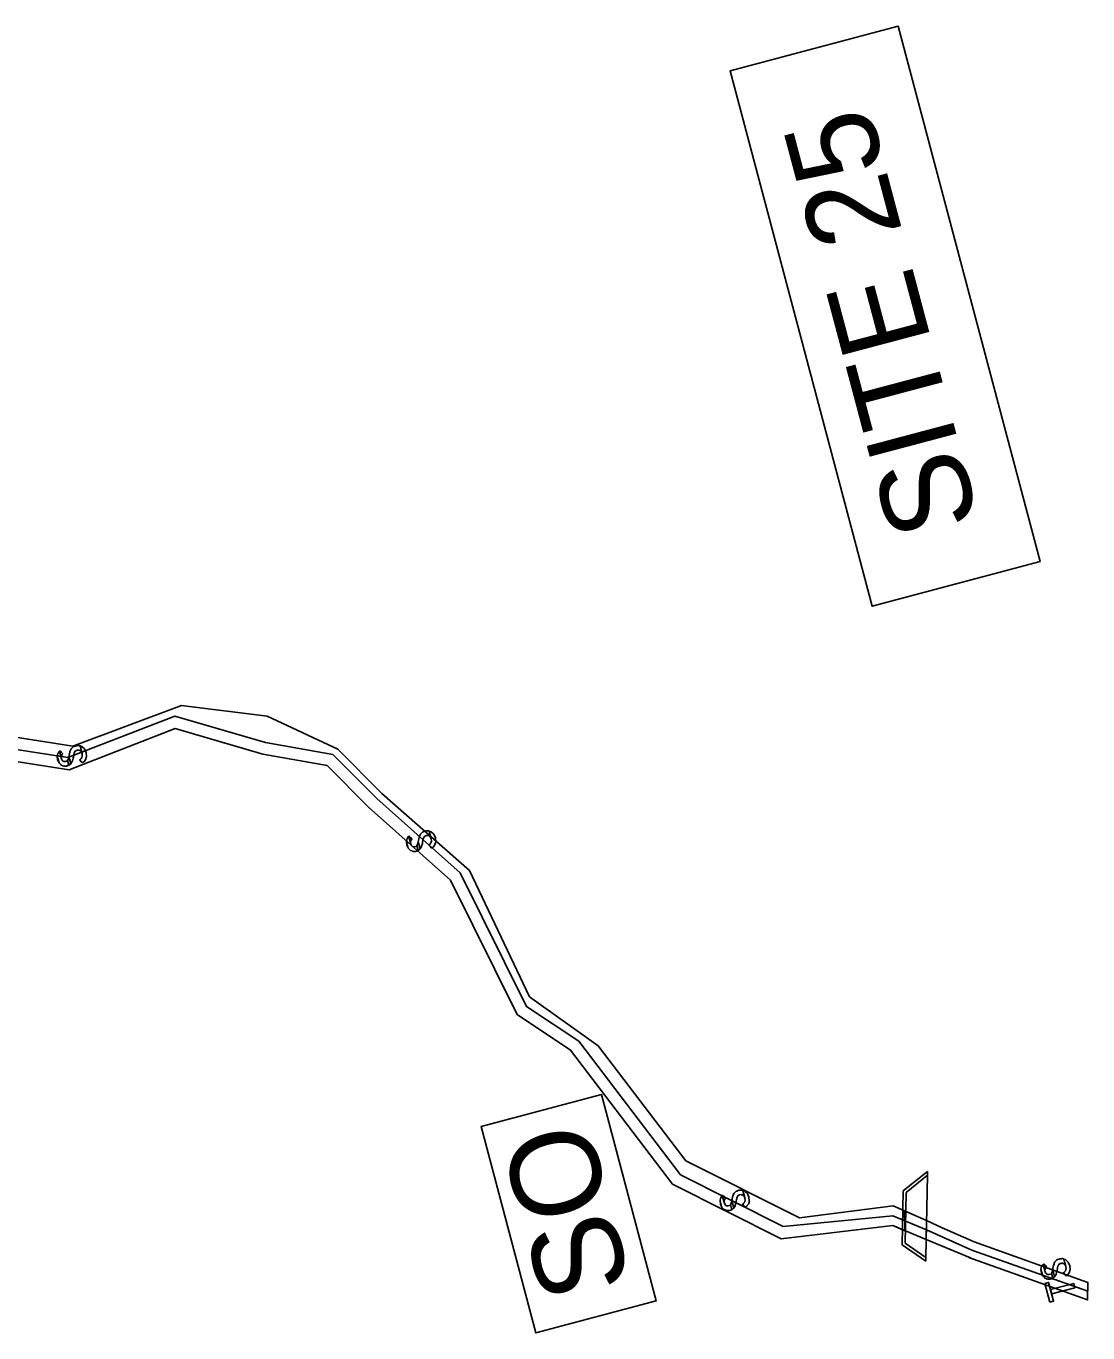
# Model space of a CAD drawing. Extents: x 474218 to 481634, y 484357 to 504997.
# Drawn here: x 474683.1 to 474860.7, y 503504.1 to 503722.6 of the extents above; entities that cross this region are included whole.
import ezdxf

# ---------------------------------------------------------------- set-up
doc = ezdxf.new("R2010")
doc.units = 0
for name, color, linetype in [('Exist Hydro Jurisdictional Stream or Body of Water', 7, 'Continuous'), ('Old_Level_29', 7, 'Continuous'), ('Prop Earthen Structure Impacts In Surface Waters Hatching CELL', 7, 'Continuous'), ('Prop Grid Mask', 7, 'Continuous'), ('Scratch_Level_4', 7, 'Continuous'), ('Temp Earthen Structure Impacts In Surface Waters Hatching CELL', 7, 'Continuous')]:
    doc.layers.add(name, color=color, linetype=linetype)

msp = doc.modelspace()

# ---------------------------------------------------------------- linework, layer by layer
at = {"layer": 'Exist Hydro Jurisdictional Stream or Body of Water'}
msp.add_lwpolyline([(474768.41, 503504.07), (474759.25, 503538.58), (474779.37, 503543.93), (474788.54, 503509.41)], close=True, dxfattribs=at)
at = {"layer": 'Old_Level_29'}
msp.add_lwpolyline([(474824.67, 503625.6), (474800.88, 503715.15), (474828.99, 503722.62), (474852.78, 503633.07)], close=True, dxfattribs=at)
at = {"layer": 'Prop Earthen Structure Impacts In Surface Waters Hatching CELL'}
msp.add_line((474833.71, 503519.66), (474833.77, 503522.84), dxfattribs=at)
for points in [[(474833.77, 503522.84), (474828.15, 503525.32), (474812.53, 503523.33), (474793.51, 503532.82), (474778.81, 503552.07), (474767.33, 503560.28), (474757.3, 503581.41), (474742.63, 503594.3), (474735.29, 503601.71), (474723.46, 503607.23), (474709.13, 503608.98), (474690.95, 503602.21), (474676.66, 503604.42)], [(474676.08, 503600.47), (474690.35, 503598.26), (474708.09, 503605.12), (474722.74, 503600.88), (474733.47, 503598.97), (474740.42, 503591.99), (474754.12, 503579.78), (474765.26, 503557.3), (474774.22, 503551.36), (474791.27, 503528.92), (474809.41, 503519.82), (474828.1, 503522), (474833.71, 503519.66)]]:
    msp.add_lwpolyline(points, dxfattribs=at)
for points in [[(474690.14, 503598.94), (474690.3, 503598.99), (474690.07, 503599.85), (474689.93, 503599.71), (474689.68, 503599.62), (474689.67, 503599.62), (474689.6, 503599.62), (474689.42, 503599.64), (474689.35, 503599.7), (474689.25, 503599.76), (474689.2, 503599.8), (474689.18, 503599.83), (474689.12, 503599.93), (474689.05, 503600.07), (474688.71, 503601.33), (474688.65, 503601.27), (474688.47, 503601.01), (474688.43, 503600.95), (474688.34, 503600.51), (474688.64, 503599.38), (474688.92, 503599.1), (474689, 503599.03), (474689.27, 503598.92), (474689.36, 503598.88), (474689.41, 503598.86), (474689.44, 503598.85), (474689.45, 503598.85), (474689.49, 503598.85), (474689.57, 503598.85), (474689.63, 503598.85), (474689.81, 503598.85), (474689.87, 503598.85), (474689.89, 503598.85)], [(474689.13, 503600.74), (474689.26, 503600.92), (474689.01, 503601.19), (474688.93, 503601.28), (474688.81, 503601.41), (474688.78, 503601.38), (474688.77, 503601.38), (474688.75, 503601.36), (474688.71, 503601.33), (474689.05, 503600.07), (474689, 503600.4), (474689.02, 503600.45), (474689.02, 503600.47), (474689.04, 503600.54), (474689.09, 503600.68)], [(474692.36, 503601.23), (474692.49, 503600.96), (474692.15, 503602.23), (474692.09, 503602.25), (474692.09, 503602.25), (474692.07, 503602.25), (474691.97, 503602.29), (474691.93, 503602.29), (474691.9, 503602.29), (474691.76, 503602.28), (474691.7, 503602.28), (474691.65, 503602.27), (474691.47, 503602.26), (474691.37, 503602.22), (474691.12, 503602.13), (474691.01, 503602.09), (474690.93, 503602.01), (474690.79, 503601.87), (474690.79, 503601.87), (474690.67, 503601.76), (474690.61, 503601.62), (474690.47, 503601.28), (474690.44, 503601.17), (474690.34, 503600.71), (474690.3, 503600.48), (474690.62, 503599.26), (474690.69, 503599.38), (474690.85, 503599.65), (474690.87, 503599.74), (474691, 503600.18), (474691.04, 503600.38), (474691.1, 503600.7), (474691.18, 503601.08), (474691.25, 503601.19), (474691.33, 503601.33), (474691.57, 503601.48), (474691.67, 503601.5), (474691.85, 503601.52), (474691.9, 503601.51), (474691.97, 503601.5), (474692.12, 503601.46), (474692.16, 503601.43), (474692.21, 503601.38), (474692.34, 503601.27), (474692.35, 503601.25)], [(474693.23, 503600.46), (474693.17, 503601.11), (474692.9, 503601.73), (474692.9, 503601.73), (474692.5, 503602.09), (474692.45, 503602.13), (474692.15, 503602.23), (474692.49, 503600.96), (474692.53, 503600.61), (474692.53, 503600.6), (474692.52, 503600.58), (474692.48, 503600.38), (474692.46, 503600.3), (474692.44, 503600.27), (474692.33, 503600.13), (474692.29, 503600.06), (474692.25, 503600.03), (474692.1, 503599.92), (474692.36, 503599.6), (474692.43, 503599.52), (474692.52, 503599.41), (474692.64, 503599.49), (474692.67, 503599.51), (474692.7, 503599.53), (474692.78, 503599.58), (474692.79, 503599.59), (474692.8, 503599.59), (474692.84, 503599.64), (474693.05, 503599.9), (474693.07, 503599.93), (474693.23, 503600.45)], [(474688.62, 503599.44), (474688.64, 503599.38), (474688.34, 503600.51), (474688.34, 503600.49), (474688.41, 503599.91), (474688.41, 503599.91)], [(474690.54, 503599.19), (474690.62, 503599.27), (474690.3, 503600.48), (474690.26, 503600.23), (474690.14, 503599.92), (474690.07, 503599.85), (474690.3, 503598.99), (474690.37, 503599.05)], [(474750.78, 503586.97), (474750.91, 503586.7), (474750.57, 503587.97), (474750.51, 503587.99), (474750.51, 503587.99), (474750.5, 503587.99), (474750.39, 503588.03), (474750.35, 503588.02), (474750.32, 503588.02), (474750.18, 503588.01), (474750.12, 503588.01), (474750.07, 503588.01), (474749.89, 503588), (474749.79, 503587.96), (474749.54, 503587.87), (474749.43, 503587.82), (474749.36, 503587.75), (474749.21, 503587.61), (474749.21, 503587.61), (474749.09, 503587.49), (474749.03, 503587.35), (474748.89, 503587.02), (474748.86, 503586.91), (474748.76, 503586.45), (474748.72, 503586.21), (474749.04, 503585), (474749.11, 503585.12), (474749.27, 503585.39), (474749.3, 503585.48), (474749.42, 503585.91), (474749.46, 503586.12), (474749.52, 503586.43), (474749.6, 503586.81), (474749.67, 503586.93), (474749.75, 503587.07), (474749.99, 503587.22), (474750.09, 503587.23), (474750.27, 503587.26), (474750.32, 503587.25), (474750.39, 503587.23), (474750.54, 503587.2), (474750.58, 503587.16), (474750.63, 503587.12), (474750.76, 503587), (474750.77, 503586.99)], [(474751.65, 503586.2), (474751.59, 503586.85), (474751.32, 503587.46), (474751.32, 503587.46), (474750.92, 503587.82), (474750.87, 503587.87), (474750.57, 503587.97), (474750.91, 503586.7), (474750.95, 503586.35), (474750.95, 503586.34), (474750.94, 503586.31), (474750.9, 503586.12), (474750.88, 503586.04), (474750.86, 503586.01), (474750.75, 503585.86), (474750.71, 503585.8), (474750.67, 503585.77), (474750.52, 503585.66), (474750.78, 503585.34), (474750.85, 503585.26), (474750.94, 503585.15), (474751.07, 503585.23), (474751.09, 503585.24), (474751.12, 503585.26), (474751.21, 503585.32), (474751.22, 503585.33), (474751.22, 503585.33), (474751.26, 503585.38), (474751.47, 503585.63), (474751.49, 503585.67), (474751.66, 503586.19)], [(474748.56, 503584.67), (474748.72, 503584.73), (474748.49, 503585.59), (474748.35, 503585.44), (474748.1, 503585.36), (474748.09, 503585.35), (474748.02, 503585.36), (474747.84, 503585.38), (474747.77, 503585.43), (474747.67, 503585.5), (474747.62, 503585.53), (474747.6, 503585.56), (474747.55, 503585.67), (474747.47, 503585.81), (474747.13, 503587.06), (474747.07, 503587.01), (474746.89, 503586.74), (474746.85, 503586.68), (474746.76, 503586.24), (474747.06, 503585.12), (474747.34, 503584.84), (474747.42, 503584.76), (474747.69, 503584.66), (474747.78, 503584.62), (474747.83, 503584.6), (474747.86, 503584.59), (474747.87, 503584.59), (474747.91, 503584.59), (474747.99, 503584.59), (474748.05, 503584.59), (474748.23, 503584.59), (474748.29, 503584.59), (474748.31, 503584.59)], [(474747.04, 503585.17), (474747.06, 503585.12), (474746.76, 503586.24), (474746.76, 503586.23), (474746.83, 503585.65), (474746.83, 503585.64)], [(474747.55, 503586.48), (474747.68, 503586.65), (474747.43, 503586.93), (474747.35, 503587.02), (474747.23, 503587.15), (474747.2, 503587.12), (474747.19, 503587.11), (474747.17, 503587.09), (474747.13, 503587.06), (474747.47, 503585.81), (474747.42, 503586.14), (474747.44, 503586.19), (474747.44, 503586.21), (474747.46, 503586.27), (474747.51, 503586.42)], [(474748.96, 503584.93), (474749.04, 503585), (474748.72, 503586.21), (474748.68, 503585.97), (474748.56, 503585.65), (474748.49, 503585.59), (474748.72, 503584.73), (474748.79, 503584.78)], [(474801.02, 503524.6), (474801.18, 503524.66), (474800.95, 503525.51), (474800.81, 503525.37), (474800.56, 503525.29), (474800.55, 503525.28), (474800.48, 503525.29), (474800.3, 503525.31), (474800.23, 503525.36), (474800.13, 503525.43), (474800.08, 503525.46), (474800.06, 503525.49), (474800.01, 503525.6), (474799.93, 503525.74), (474799.59, 503526.99), (474799.53, 503526.94), (474799.35, 503526.67), (474799.31, 503526.61), (474799.22, 503526.17), (474799.52, 503525.05), (474799.8, 503524.77), (474799.88, 503524.69), (474800.15, 503524.58), (474800.24, 503524.55), (474800.29, 503524.53), (474800.32, 503524.51), (474800.33, 503524.51), (474800.37, 503524.51), (474800.45, 503524.51), (474800.51, 503524.51), (474800.69, 503524.52), (474800.75, 503524.51), (474800.77, 503524.52)], [(474800.01, 503526.41), (474800.14, 503526.58), (474799.89, 503526.85), (474799.81, 503526.95), (474799.69, 503527.07), (474799.66, 503527.05), (474799.65, 503527.04), (474799.63, 503527.02), (474799.59, 503526.99), (474799.93, 503525.74), (474799.88, 503526.07), (474799.9, 503526.12), (474799.9, 503526.14), (474799.92, 503526.2), (474799.97, 503526.35)], [(474803.24, 503526.9), (474803.37, 503526.63), (474803.03, 503527.89), (474802.97, 503527.91), (474802.97, 503527.91), (474802.96, 503527.92), (474802.85, 503527.95), (474802.81, 503527.95), (474802.78, 503527.95), (474802.64, 503527.94), (474802.58, 503527.94), (474802.53, 503527.94), (474802.35, 503527.93), (474802.25, 503527.89), (474802, 503527.79), (474801.89, 503527.75), (474801.82, 503527.68), (474801.67, 503527.53), (474801.67, 503527.53), (474801.55, 503527.42), (474801.49, 503527.28), (474801.35, 503526.94), (474801.32, 503526.84), (474801.22, 503526.38), (474801.18, 503526.14), (474801.5, 503524.93), (474801.57, 503525.05), (474801.73, 503525.31), (474801.76, 503525.41), (474801.88, 503525.84), (474801.92, 503526.05), (474801.98, 503526.36), (474802.06, 503526.74), (474802.13, 503526.85), (474802.21, 503526.99), (474802.45, 503527.14), (474802.55, 503527.16), (474802.73, 503527.19), (474802.78, 503527.18), (474802.85, 503527.16), (474803, 503527.13), (474803.04, 503527.09), (474803.09, 503527.05), (474803.22, 503526.93), (474803.23, 503526.92)], [(474804.11, 503526.13), (474804.05, 503526.78), (474803.78, 503527.39), (474803.78, 503527.39), (474803.38, 503527.75), (474803.33, 503527.8), (474803.03, 503527.89), (474803.37, 503526.63), (474803.41, 503526.27), (474803.41, 503526.27), (474803.4, 503526.24), (474803.36, 503526.04), (474803.34, 503525.97), (474803.32, 503525.94), (474803.21, 503525.79), (474803.17, 503525.73), (474803.13, 503525.7), (474802.98, 503525.59), (474803.24, 503525.27), (474803.31, 503525.18), (474803.4, 503525.08), (474803.53, 503525.15), (474803.55, 503525.17), (474803.58, 503525.19), (474803.67, 503525.25), (474803.68, 503525.26), (474803.68, 503525.26), (474803.72, 503525.31), (474803.93, 503525.56), (474803.95, 503525.59), (474804.12, 503526.12)], [(474799.5, 503525.1), (474799.52, 503525.05), (474799.22, 503526.17), (474799.22, 503526.15), (474799.29, 503525.57), (474799.29, 503525.57)], [(474801.42, 503524.86), (474801.5, 503524.93), (474801.18, 503526.14), (474801.14, 503525.9), (474801.02, 503525.58), (474800.95, 503525.52), (474801.18, 503524.66), (474801.25, 503524.71)]]:
    msp.add_lwpolyline(points, close=True, dxfattribs=at)
at = {"layer": 'Prop Grid Mask'}
for points in [[(474852.78, 503633.07), (474828.99, 503722.62), (474800.88, 503715.15), (474824.67, 503625.6)], [(474788.54, 503509.41), (474779.37, 503543.93), (474759.25, 503538.58), (474768.41, 503504.07)]]:
    msp.add_lwpolyline(points, close=True, dxfattribs=at)
at = {"layer": 'Scratch_Level_4'}
for p, q in [((474833.92, 503531.08), (474829.86, 503527.8)), ((474830.36, 503527.56), (474833.91, 503530.42)), ((474833.66, 503516.68), (474833.91, 503530.42)), ((474833.91, 503530.42), (474833.92, 503531.08)), ((474829.86, 503527.8), (474829.69, 503518.81)), ((474830.2, 503519.06), (474830.36, 503527.56)), ((474830.06, 503524.48), (474830.14, 503521.15)), ((474829.69, 503518.81), (474833.64, 503516.08)), ((474833.66, 503516.68), (474830.2, 503519.06)), ((474833.64, 503516.08), (474833.66, 503516.68))]:
    msp.add_line(p, q, dxfattribs=at)
for points in [[(474676.66, 503604.42), (474690.95, 503602.21), (474709.13, 503608.98), (474723.46, 503607.23), (474735.29, 503601.71), (474742.63, 503594.3), (474757.3, 503581.41), (474767.33, 503560.28), (474778.81, 503552.07), (474793.51, 503532.82), (474812.53, 503523.33), (474828.15, 503525.32), (474830.06, 503524.48)], [(474833.74, 503521.3), (474828.12, 503523.63), (474809.78, 503521.88), (474792.58, 503530.5), (474775.6, 503552.84), (474766.82, 503558.67), (474755.74, 503581.02), (474741.8, 503593.44), (474734.44, 503600.82), (474723.19, 503602.83), (474708, 503607.23), (474690.12, 503600.32), (474676.39, 503602.44)], [(474830.14, 503521.15), (474828.1, 503522), (474809.41, 503519.82), (474791.27, 503528.92), (474774.22, 503551.36), (474765.26, 503557.3), (474754.12, 503579.78), (474740.42, 503591.99), (474733.47, 503598.97), (474722.74, 503600.88), (474708.09, 503605.12), (474690.35, 503598.26), (474676.08, 503600.47)], [(474860.72, 503511.06), (474841.35, 503517.89), (474833.74, 503521.3)]]:
    msp.add_lwpolyline(points, dxfattribs=at)
at = {"layer": 'Temp Earthen Structure Impacts In Surface Waters Hatching CELL'}
msp.add_lwpolyline([(474833.71, 503519.66), (474841.09, 503516.59), (474840.81, 503516.69), (474860.7, 503509.57), (474860.74, 503512.5), (474841.74, 503519.29), (474836.39, 503521.64), (474833.77, 503522.84), (474833.71, 503519.66)], dxfattribs=at)
for points in [[(474856.92, 503515.43), (474857.05, 503515.16), (474856.71, 503516.42), (474856.65, 503516.44), (474856.65, 503516.44), (474856.63, 503516.45), (474856.53, 503516.48), (474856.49, 503516.48), (474856.46, 503516.48), (474856.32, 503516.47), (474856.26, 503516.47), (474856.21, 503516.47), (474856.03, 503516.46), (474855.93, 503516.42), (474855.68, 503516.32), (474855.57, 503516.28), (474855.49, 503516.21), (474855.35, 503516.06), (474855.35, 503516.06), (474855.23, 503515.95), (474855.17, 503515.81), (474855.03, 503515.47), (474855, 503515.37), (474854.9, 503514.91), (474854.86, 503514.67), (474855.18, 503513.46), (474855.25, 503513.58), (474855.41, 503513.84), (474855.43, 503513.94), (474855.56, 503514.37), (474855.6, 503514.58), (474855.66, 503514.89), (474855.74, 503515.27), (474855.81, 503515.38), (474855.89, 503515.52), (474856.13, 503515.67), (474856.23, 503515.69), (474856.41, 503515.72), (474856.46, 503515.7), (474856.53, 503515.69), (474856.68, 503515.66), (474856.72, 503515.62), (474856.77, 503515.58), (474856.9, 503515.46), (474856.91, 503515.45)], [(474857.79, 503514.66), (474857.73, 503515.3), (474857.46, 503515.92), (474857.46, 503515.92), (474857.06, 503516.28), (474857.01, 503516.32), (474856.71, 503516.42), (474857.05, 503515.16), (474857.09, 503514.8), (474857.09, 503514.8), (474857.08, 503514.77), (474857.04, 503514.57), (474857.02, 503514.5), (474857, 503514.47), (474856.89, 503514.32), (474856.85, 503514.26), (474856.81, 503514.23), (474856.66, 503514.12), (474856.92, 503513.8), (474856.99, 503513.71), (474857.08, 503513.6), (474857.2, 503513.68), (474857.23, 503513.7), (474857.26, 503513.72), (474857.34, 503513.77), (474857.35, 503513.79), (474857.36, 503513.79), (474857.4, 503513.84), (474857.61, 503514.09), (474857.63, 503514.12), (474857.79, 503514.65)], [(474854.7, 503513.13), (474854.86, 503513.19), (474854.63, 503514.04), (474854.49, 503513.9), (474854.24, 503513.82), (474854.23, 503513.81), (474854.16, 503513.82), (474853.98, 503513.84), (474853.91, 503513.89), (474853.81, 503513.96), (474853.76, 503513.99), (474853.74, 503514.02), (474853.68, 503514.13), (474853.61, 503514.27), (474853.27, 503515.52), (474853.21, 503515.47), (474853.03, 503515.2), (474852.99, 503515.14), (474852.9, 503514.7), (474853.2, 503513.58), (474853.48, 503513.3), (474853.56, 503513.22), (474853.83, 503513.11), (474853.92, 503513.08), (474853.97, 503513.06), (474854, 503513.04), (474854.01, 503513.04), (474854.05, 503513.04), (474854.13, 503513.04), (474854.19, 503513.04), (474854.37, 503513.04), (474854.43, 503513.04), (474854.45, 503513.04)], [(474853.18, 503513.63), (474853.2, 503513.58), (474852.9, 503514.7), (474852.9, 503514.68), (474852.97, 503514.1), (474852.97, 503514.1)], [(474853.69, 503514.93), (474853.82, 503515.11), (474853.57, 503515.38), (474853.49, 503515.48), (474853.37, 503515.6), (474853.34, 503515.58), (474853.33, 503515.57), (474853.31, 503515.55), (474853.27, 503515.52), (474853.61, 503514.27), (474853.56, 503514.59), (474853.58, 503514.65), (474853.58, 503514.67), (474853.6, 503514.73), (474853.65, 503514.88)], [(474855.1, 503513.39), (474855.18, 503513.46), (474854.86, 503514.67), (474854.82, 503514.43), (474854.7, 503514.11), (474854.63, 503514.04), (474854.86, 503513.19), (474854.93, 503513.24)], [(474854.38, 503509.2), (474855.01, 503509.37), (474854.18, 503512.51), (474853.55, 503512.34)], [(474854.69, 503510.57), (474858.58, 503511.61), (474858.39, 503512.34), (474854.49, 503511.31)]]:
    msp.add_lwpolyline(points, close=True, dxfattribs=at)

# ---------------------------------------------------------------- texts
at = {"layer": 'Exist Hydro Jurisdictional Stream or Body of Water'}
msp.add_text('SO', height=15, rotation=104.8782, dxfattribs=at).set_placement((474784.41, 503512.2))
at = {"layer": 'Old_Level_29'}
msp.add_text('SITE 25', height=15, rotation=104.8782, dxfattribs=at).set_placement((474842.65, 503639.73))

doc.saveas('drawing.dxf')
